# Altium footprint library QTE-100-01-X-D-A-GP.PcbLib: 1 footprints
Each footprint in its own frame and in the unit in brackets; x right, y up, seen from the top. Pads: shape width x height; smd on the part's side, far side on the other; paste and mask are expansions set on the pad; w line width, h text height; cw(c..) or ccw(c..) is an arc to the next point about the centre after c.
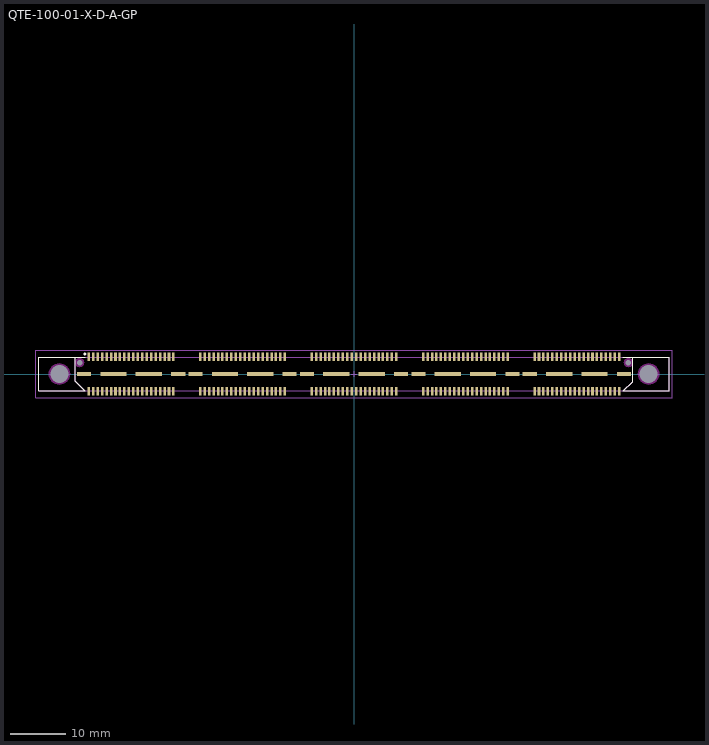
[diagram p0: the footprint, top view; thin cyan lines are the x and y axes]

## QTE-100-01-X-D-A-GP [mm] "0.80mm pitch, 200 pin, high speed terminal strip; w/guide posts"
height 4.27
pads (224):
  rect 0.45x1.45 smd mask+0: 1(-47.6,3.09) 2(-47.6,-3.09) 3(-46.8,3.09) 4(-46.8,-3.09) 5(-46,3.09) 6(-46,-3.09) 7(-45.2,3.09) 8(-45.2,-3.09) 9(-44.4,3.09) 10(-44.4,-3.09) 11(-43.6,3.09) 12(-43.6,-3.09) 13(-42.8,3.09) 14(-42.8,-3.09) 15(-42,3.09) 16(-42,-3.09) 17(-41.2,3.09) 18(-41.2,-3.09) 19(-40.4,3.09) 20(-40.4,-3.09) 21(-39.6,3.09) 22(-39.6,-3.09) 23(-38.8,3.09) 24(-38.8,-3.09) 25(-38,3.09) 26(-38,-3.09) 27(-37.2,3.09) 28(-37.2,-3.09) 29(-36.4,3.09) 30(-36.4,-3.09) 31(-35.6,3.09) 32(-35.6,-3.09) 33(-34.8,3.09) 34(-34.8,-3.09) 35(-34,3.09) 36(-34,-3.09) 37(-33.2,3.09) 38(-33.2,-3.09) 39(-32.4,3.09) 40(-32.4,-3.09) 41(-27.6,3.09) 42(-27.6,-3.09) 43(-26.8,3.09) 44(-26.8,-3.09) 45(-26,3.09) 46(-26,-3.09) 47(-25.2,3.09) 48(-25.2,-3.09) 49(-24.4,3.09) 50(-24.4,-3.09) 51(-23.6,3.09) 52(-23.6,-3.09) 53(-22.8,3.09) 54(-22.8,-3.09) 55(-22,3.09) 56(-22,-3.09) 57(-21.2,3.09) 58(-21.2,-3.09) 59(-20.4,3.09) 60(-20.4,-3.09) 61(-19.6,3.09) 62(-19.6,-3.09) 63(-18.8,3.09) 64(-18.8,-3.09) 65(-18,3.09) 66(-18,-3.09) 67(-17.2,3.09) 68(-17.2,-3.09) 69(-16.4,3.09) 70(-16.4,-3.09) 71(-15.6,3.09) 72(-15.6,-3.09) 73(-14.8,3.09) 74(-14.8,-3.09) 75(-14,3.09) 76(-14,-3.09) 77(-13.2,3.09) 78(-13.2,-3.09) 79(-12.4,3.09) 80(-12.4,-3.09) 81(-7.6,3.09) 82(-7.6,-3.09) 83(-6.8,3.09) 84(-6.8,-3.09) 85(-6,3.09) 86(-6,-3.09) 87(-5.2,3.09) 88(-5.2,-3.09) 89(-4.4,3.09) 90(-4.4,-3.09) 91(-3.6,3.09) 92(-3.6,-3.09) 93(-2.8,3.09) 94(-2.8,-3.09) 95(-2,3.09) 96(-2,-3.09) 97(-1.2,3.09) 98(-1.2,-3.09) 99(-0.4,3.09) 100(-0.4,-3.09) 101(0.4,3.09) 102(0.4,-3.09) 103(1.2,3.09) 104(1.2,-3.09) 105(2,3.09) 106(2,-3.09) 107(2.8,3.09) 108(2.8,-3.09) 109(3.6,3.09) 110(3.6,-3.09) 111(4.4,3.09) 112(4.4,-3.09) 113(5.2,3.09) 114(5.2,-3.09) 115(6,3.09) 116(6,-3.09) 117(6.8,3.09) 118(6.8,-3.09) 119(7.6,3.09) 120(7.6,-3.09) 121(12.4,3.09) 122(12.4,-3.09) 123(13.2,3.09) 124(13.2,-3.09) 125(14,3.09) 126(14,-3.09) 127(14.8,3.09) 128(14.8,-3.09) 129(15.6,3.09) 130(15.6,-3.09) 131(16.4,3.09) 132(16.4,-3.09) 133(17.2,3.09) 134(17.2,-3.09) 135(18,3.09) 136(18,-3.09) 137(18.8,3.09) 138(18.8,-3.09) 139(19.6,3.09) 140(19.6,-3.09) 141(20.4,3.09) 142(20.4,-3.09) 143(21.2,3.09) 144(21.2,-3.09) 145(22,3.09) 146(22,-3.09) 147(22.8,3.09) 148(22.8,-3.09) 149(23.6,3.09) 150(23.6,-3.09) 151(24.4,3.09) 152(24.4,-3.09) 153(25.2,3.09) 154(25.2,-3.09) 155(26,3.09) 156(26,-3.09) 157(26.8,3.09) 158(26.8,-3.09) 159(27.6,3.09) 160(27.6,-3.09) 161(32.4,3.09) 162(32.4,-3.09) 163(33.2,3.09) 164(33.2,-3.09) 165(34,3.09) 166(34,-3.09) 167(34.8,3.09) 168(34.8,-3.09) 169(35.6,3.09) 170(35.6,-3.09) 171(36.4,3.09) 172(36.4,-3.09) 173(37.2,3.09) 174(37.2,-3.09) 175(38,3.09) 176(38,-3.09) 177(38.8,3.09) 178(38.8,-3.09) 179(39.6,3.09) 180(39.6,-3.09) 181(40.4,3.09) 182(40.4,-3.09) 183(41.2,3.09) 184(41.2,-3.09) 185(42,3.09) 186(42,-3.09) 187(42.8,3.09) 188(42.8,-3.09) 189(43.6,3.09) 190(43.6,-3.09) 191(44.4,3.09) 192(44.4,-3.09) 193(45.2,3.09) 194(45.2,-3.09) 195(46,3.09) 196(46,-3.09) 197(46.8,3.09) 198(46.8,-3.09) 199(47.6,3.09) 200(47.6,-3.09)
  rect 2.55x0.65 smd mask+0: 201(-48.445,0) 204(-31.555,0) 205(-28.445,0) 208(-11.555,0) 209(-8.445,0) 212(8.445,0) 213(11.555,0) 216(28.445,0) 217(31.555,0) 220(48.445,0)
  rect 4.7x0.65 smd mask+0: 202(-43.175,0) 203(-36.825,0) 206(-23.175,0) 207(-16.825,0) 210(-3.175,0) 211(3.175,0) 214(16.825,0) 215(23.175,0) 218(36.825,0) 219(43.175,0)
  round 0.5 hole 1 unplated mask+0: 221(-49.24,2.04) 222(49.24,2.04)
  round 1 hole 3.2 unplated mask+0: 223(-52.867,0) 224(52.867,0)
Top Overlay:
  circle w0.25: c-48.3,3.6 r0.125
  lines w0.2: -50.05,3 -50.05,-1.3 -48.35,-3 ; -48.2,-3 -56.6,-3 -56.6,3 -48.2,3 ; 48.2,-3 56.6,-3 56.6,3 48.25,3 ; 48.35,-3 50,-1.35 50,3
Keep-Out Layer:
  pour cut-out: 54.777,0 54.741,0.372 54.632,0.731 54.455,1.061 54.218,1.35 53.929,1.587 53.599,1.764 53.24,1.873 52.868,1.909 52.496,1.873 52.137,1.764 51.807,1.587 51.518,1.35 51.281,1.061 51.104,0.731 50.995,0.372 50.959,0 50.995,-0.372 51.104,-0.731 51.281,-1.061 51.518,-1.35 51.807,-1.587 52.137,-1.764 52.496,-1.873 52.868,-1.909 53.24,-1.873 53.599,-1.764 53.929,-1.587 54.218,-1.35 54.455,-1.061 54.632,-0.731 54.741,-0.372
  pour cut-out: -50.959,0 -50.995,0.372 -51.104,0.731 -51.281,1.061 -51.518,1.35 -51.807,1.587 -52.137,1.764 -52.496,1.873 -52.868,1.909 -53.24,1.873 -53.599,1.764 -53.929,1.587 -54.218,1.35 -54.455,1.061 -54.632,0.731 -54.741,0.372 -54.777,0 -54.741,-0.372 -54.632,-0.731 -54.455,-1.061 -54.218,-1.35 -53.929,-1.587 -53.599,-1.764 -53.24,-1.873 -52.868,-1.909 -52.496,-1.873 -52.137,-1.764 -51.807,-1.587 -51.518,-1.35 -51.281,-1.061 -51.104,-0.731 -50.995,-0.372
  pour cut-out: 50.047,2.04 50.019,2.249 49.939,2.443 49.811,2.611 49.643,2.739 49.449,2.819 49.24,2.847 49.031,2.819 48.837,2.739 48.669,2.611 48.541,2.443 48.461,2.249 48.433,2.04 48.461,1.831 48.541,1.637 48.669,1.469 48.837,1.341 49.031,1.261 49.24,1.233 49.449,1.261 49.643,1.341 49.811,1.469 49.939,1.637 50.019,1.831
  pour cut-out: -48.433,2.04 -48.461,2.249 -48.541,2.443 -48.669,2.611 -48.837,2.739 -49.031,2.819 -49.24,2.847 -49.449,2.819 -49.643,2.739 -49.811,2.611 -49.939,2.443 -50.019,2.249 -50.047,2.04 -50.019,1.831 -49.939,1.637 -49.811,1.469 -49.643,1.341 -49.449,1.261 -49.24,1.233 -49.031,1.261 -48.837,1.341 -48.669,1.469 -48.541,1.637 -48.461,1.831
Mechanical 13:
  lines w0.1: -50,3 -56.6,3 -56.6,-3 -48.35,-3 ; 48.3,-3 56.6,-3 56.6,3 50,3 ; -48.35,-3 48.35,-3 50,-1.35 50,3 ; -48.35,-3 -50.05,-1.3 -50.05,3 50,3
  text ".Designator" at 0.127,-0.127 h1.52
Mechanical 15:
  lines w0.05: -0.5,0 0.5,0 ; 0,-0.5 0,0.5 ; -57.1,-4.3 -57.1,4.3 57.1,4.3 57.1,-4.3 -57.1,-4.3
